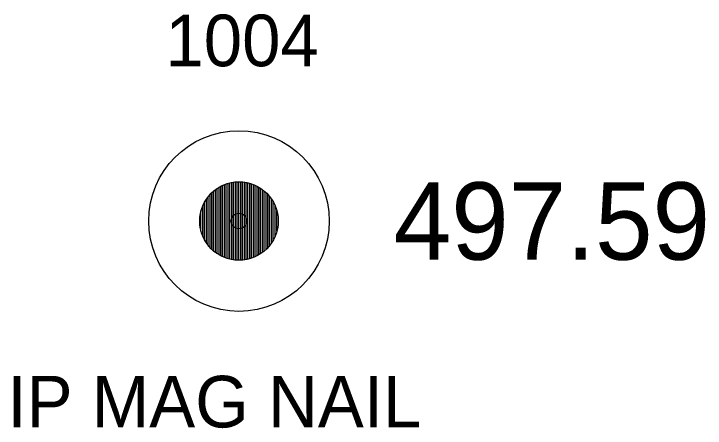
# Model space of a CAD drawing. Extents: x 1796360 to 1799195, y 895805 to 899730.
# Drawn here: x 1798301.36 to 1798314.77, y 898258.05 to 898266.08 of the extents above; entities that cross this region are included whole.
import ezdxf

# ---------------------------------------------------------------- set-up
doc = ezdxf.new("R2010")
doc.units = 0
for name, color, linetype in [('RD_EX_DV_Prop_txCode', 7, 'Continuous'), ('RD_EX_DV_PropPin', 7, 'Continuous'), ('RD_EX_TX_DV_Prop_ELEV', 7, 'Continuous'), ('RD_SMD_Locator', 7, 'Continuous')]:
    doc.layers.add(name, color=color, linetype=linetype)

msp = doc.modelspace()

# ---------------------------------------------------------------- linework, layer by layer
at = {"layer": 'RD_EX_DV_PropPin'}
for p, q in [((1798305.344, 898261.412), (1798305.344, 898262.725)), ((1798305.379, 898261.393), (1798305.379, 898262.744)), ((1798305.414, 898261.376), (1798305.414, 898262.761)), ((1798305.449, 898261.361), (1798305.449, 898262.776)), ((1798305.484, 898261.348), (1798305.484, 898262.789)), ((1798305.519, 898261.337), (1798305.519, 898262.8)), ((1798305.555, 898261.328), (1798305.555, 898262.809)), ((1798305.59, 898261.32), (1798305.59, 898262.816)), ((1798305.625, 898261.315), (1798305.625, 898262.822)), ((1798305.66, 898261.311), (1798305.66, 898262.826)), ((1798305.695, 898261.308), (1798305.695, 898262.829)), ((1798305.73, 898261.307), (1798305.73, 898262.829)), ((1798305.765, 898261.308), (1798305.765, 898262.829)), ((1798305.8, 898261.311), (1798305.8, 898262.826)), ((1798305.835, 898261.315), (1798305.835, 898262.822)), ((1798305.87, 898261.32), (1798305.87, 898262.816)), ((1798305.905, 898261.328), (1798305.905, 898262.809)), ((1798305.94, 898261.337), (1798305.94, 898262.8)), ((1798305.975, 898261.348), (1798305.975, 898262.789)), ((1798306.01, 898261.361), (1798306.01, 898262.776)), ((1798306.045, 898261.376), (1798306.045, 898262.761)), ((1798306.08, 898261.393), (1798306.08, 898262.744)), ((1798306.115, 898261.412), (1798306.115, 898262.725)), ((1798305.169, 898261.553), (1798305.169, 898262.583)), ((1798305.204, 898261.518), (1798305.204, 898262.619)), ((1798305.239, 898261.486), (1798305.239, 898262.65)), ((1798305.274, 898261.458), (1798305.274, 898262.678)), ((1798305.309, 898261.434), (1798305.309, 898262.703)), ((1798306.15, 898261.434), (1798306.15, 898262.703)), ((1798306.185, 898261.458), (1798306.185, 898262.678)), ((1798306.22, 898261.486), (1798306.22, 898262.65)), ((1798306.255, 898261.518), (1798306.255, 898262.619)), ((1798306.29, 898261.553), (1798306.29, 898262.583)), ((1798305.064, 898261.699), (1798305.064, 898262.438)), ((1798305.099, 898261.642), (1798305.099, 898262.495)), ((1798305.134, 898261.594), (1798305.134, 898262.542)), ((1798306.325, 898261.594), (1798306.325, 898262.542)), ((1798306.36, 898261.642), (1798306.36, 898262.495)), ((1798306.395, 898261.699), (1798306.395, 898262.438)), ((1798305.029, 898261.77), (1798305.029, 898262.366)), ((1798306.43, 898261.77), (1798306.43, 898262.366)), ((1798304.994, 898261.872), (1798304.994, 898262.264)), ((1798306.465, 898261.872), (1798306.465, 898262.264))]:
    msp.add_line(p, q, dxfattribs=at)
for radius in [1.75, 0.761]:
    msp.add_circle((1798305.73, 898262.068), radius, dxfattribs=at)
at = {"layer": 'RD_SMD_Locator'}
msp.add_circle((1798305.73, 898262.068), 0.15, dxfattribs=at)

# ---------------------------------------------------------------- texts
at = {"layer": 'RD_EX_DV_Prop_txCode'}
for s, p in [('1004', (1798304.304, 898265.068)), ('IP MAG NAIL', (1798301.241, 898258.068))]:
    msp.add_text(s, height=1, dxfattribs=at).set_placement(p)
at = {"layer": 'RD_EX_TX_DV_Prop_ELEV'}
msp.add_text('497.59', height=1.5, dxfattribs=at).set_placement((1798308.73, 898261.318))

doc.saveas('drawing.dxf')
